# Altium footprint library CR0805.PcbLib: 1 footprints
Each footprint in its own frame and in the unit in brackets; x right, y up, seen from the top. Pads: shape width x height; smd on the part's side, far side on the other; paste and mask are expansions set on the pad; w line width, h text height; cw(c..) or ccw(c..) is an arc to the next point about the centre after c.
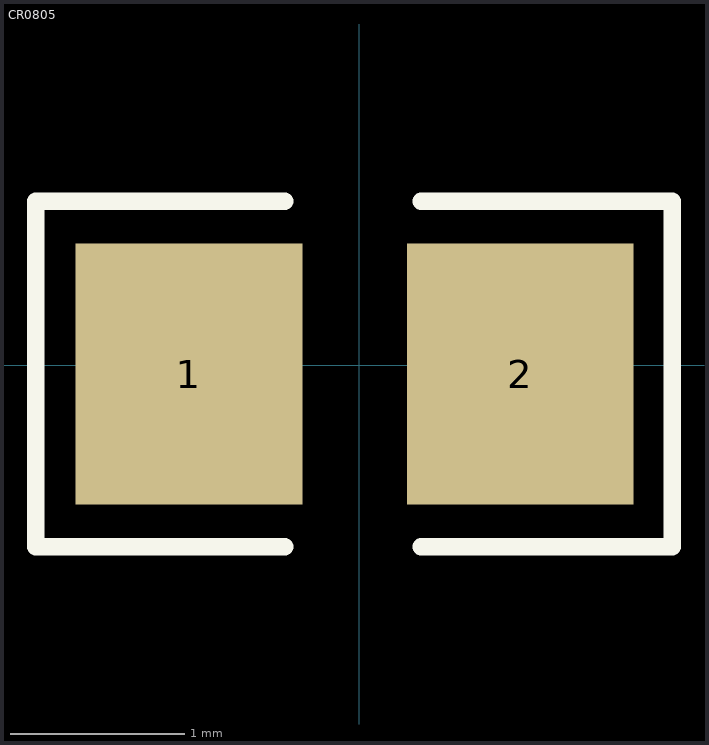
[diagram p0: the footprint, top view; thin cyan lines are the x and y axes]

## CR0805 [mm]
pads (2):
  rect 1.3x1.5 smd: 1(-0.975,-0.051) 2(0.925,-0.051)
Top Overlay:
  lines w0.1: -0.425,-1.041 -1.854,-1.041 -1.854,0.94 -0.425,0.94 ; 0.356,-1.041 1.797,-1.041 1.797,0.94 0.356,0.94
